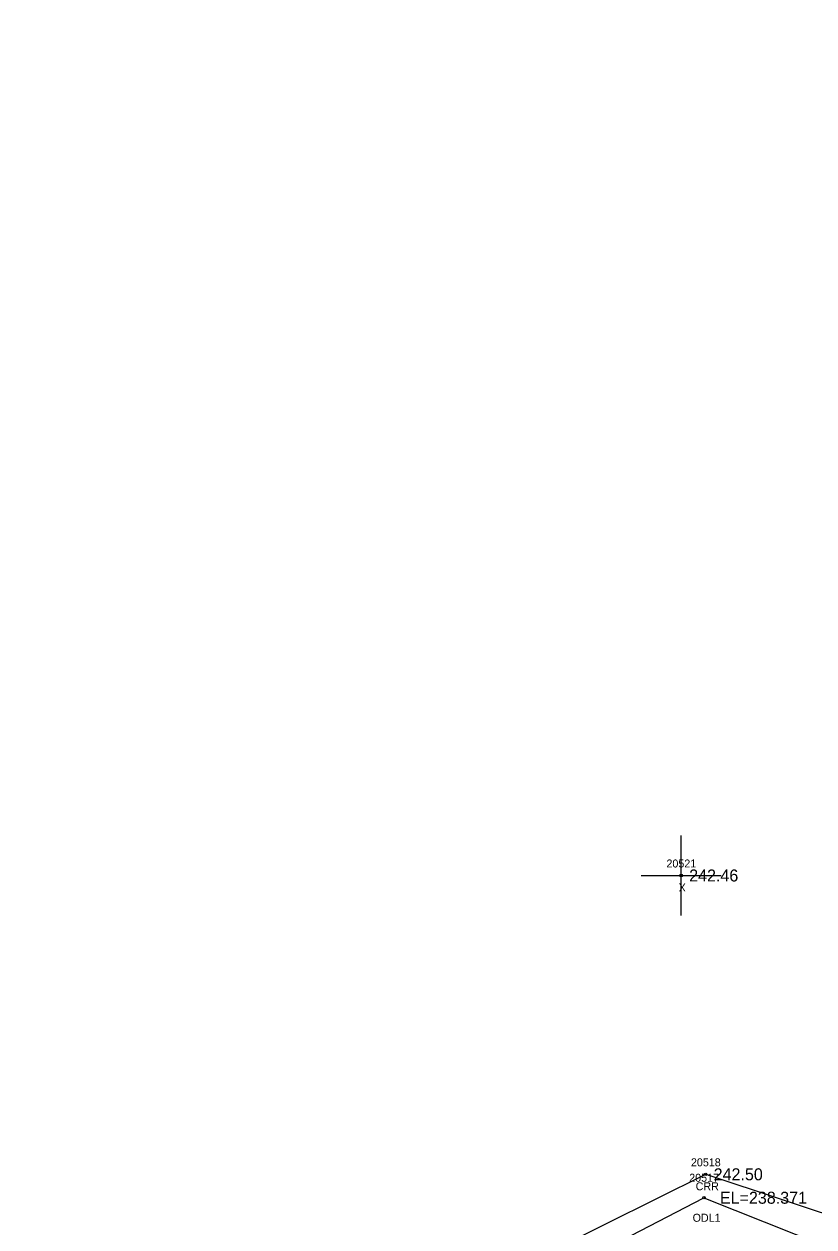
# Model space of a CAD drawing. Extents: x 2275563 to 2277161, y 1075719 to 1076412.
# Drawn here: x 2276301.2 to 2276399.9, y 1076255.2 to 1076405.6 of the extents above; entities that cross this region are included whole.
import ezdxf

# ---------------------------------------------------------------- set-up
doc = ezdxf.new("R2010")
doc.units = 0
for name, color, linetype in [('RD_EX_H2O', 7, 'Continuous'), ('RD_EX_H2O_txCode', 7, 'Continuous'), ('RD_EX_Misc', 7, 'Continuous'), ('RD_EX_Misc_txCode', 7, 'Continuous'), ('RD_EX_TX_H2O_ELEV', 7, 'Continuous'), ('RD_EX_TX_Misc_ELEV', 7, 'Continuous'), ('RD_SMD_Locator', 7, 'Continuous')]:
    doc.layers.add(name, color=color, linetype=linetype)

msp = doc.modelspace()

# ---------------------------------------------------------------- linework, layer by layer
at = {"layer": 'RD_EX_H2O'}
for points in [[(2276337.52, 1076082.32), (2276338.14, 1076090.91), (2276325.39, 1076121.38), (2276301.23, 1076176.38), (2276301.47, 1076212.03), (2276303.94, 1076212.33), (2276322.96, 1076208.7), (2276333.72, 1076197.42), (2276353.59, 1076194.54), (2276358.22, 1076208.33), (2276360.94, 1076233.4), (2276370.36, 1076250.64), (2276386.18, 1076258.85), (2276454.86, 1076231.51), (2276469.16, 1076242), (2276461.94, 1076274.88), (2276441.6, 1076298.83), (2276443.32, 1076327.87), (2276470.76, 1076362.4), (2276481.62, 1076405.55)], [(2276306.58, 1076220.1), (2276325.39, 1076214.04), (2276335.43, 1076205.2), (2276348.24, 1076201.78), (2276353.6, 1076208.85), (2276358.58, 1076232.7), (2276367.82, 1076252.56), (2276386.4, 1076261.78), (2276453.31, 1076239.6), (2276463.95, 1076245.24), (2276459.26, 1076273.53), (2276439.87, 1076297.83), (2276438.91, 1076332.85), (2276467.89, 1076361.53), (2276478.69, 1076404.9)]]:
    msp.add_lwpolyline(points, dxfattribs=at)
at = {"layer": 'RD_EX_Misc'}
for p, q in [((2276383.34, 1076294.13), (2276383.34, 1076304.13)), ((2276378.34, 1076299.13), (2276388.34, 1076299.13))]:
    msp.add_line(p, q, dxfattribs=at)
at = {"layer": 'RD_SMD_Locator'}
for centre in [(2276383.34, 1076299.13), (2276386.4, 1076261.78), (2276386.18, 1076258.85)]:
    msp.add_circle(centre, 0.15, dxfattribs=at)

# ---------------------------------------------------------------- texts
at = {"layer": 'RD_EX_H2O_txCode'}
for s, p in [('20518', (2276384.56, 1076262.78)), ('20517', (2276384.34, 1076260.85)), ('CRR', (2276385.15, 1076259.78)), ('ODL1', (2276384.77, 1076255.85))]:
    msp.add_text(s, height=1, dxfattribs=at).set_placement(p)
at = {"layer": 'RD_EX_Misc_txCode'}
for s, p in [('20521', (2276381.5, 1076300.13)), ('X', (2276383.02, 1076297.13))]:
    msp.add_text(s, height=1, dxfattribs=at).set_placement(p)
at = {"layer": 'RD_EX_TX_H2O_ELEV'}
for s, p in [('242.50', (2276387.4, 1076261.03)), ('EL=238.371', (2276388.18, 1076258.1))]:
    msp.add_text(s, height=1.5, dxfattribs=at).set_placement(p)
at = {"layer": 'RD_EX_TX_Misc_ELEV'}
msp.add_text('242.46', height=1.5, dxfattribs=at).set_placement((2276384.34, 1076298.38))

doc.saveas('drawing.dxf')
